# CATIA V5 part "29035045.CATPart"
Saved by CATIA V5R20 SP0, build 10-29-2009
Part number: 29035045
Definition: NONE
Nomenclature: 29035045
Source: Unknown
Description: 29035045
Bounding box of the stored display mesh (mm): x -22.5 to 44.548, y -31.5 to 66.048, z -21.5 to 21.5
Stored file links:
  C:\Users\Utente\Desktop\IO LAVORO\3D X SITO CF\X SITO\PLASTICA\RF1\29035045.CATPart
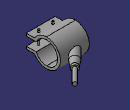
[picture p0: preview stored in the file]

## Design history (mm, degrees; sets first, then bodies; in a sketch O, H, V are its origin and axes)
Body1 "29035045" (main body)
  Solid1: solid without history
